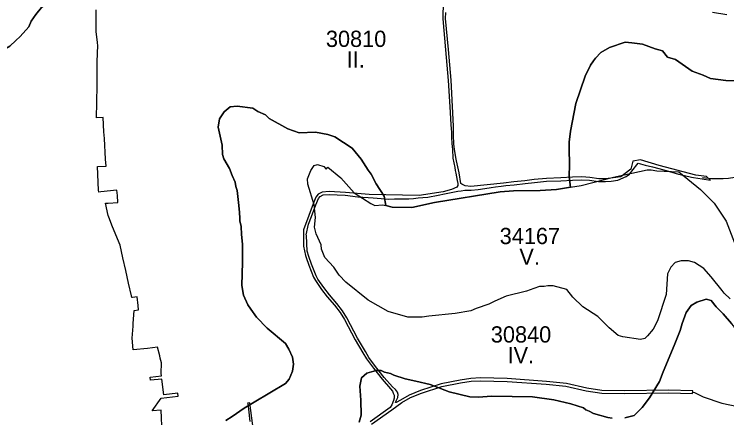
# Model space of a CAD drawing. Extents: x -555509 to -553014, y -1186753 to -1182560.
# Drawn here: x -554443 to -553565, y -1185224 to -1184728 of the extents above; entities that cross this region are included whole.
import ezdxf

# ---------------------------------------------------------------- set-up
doc = ezdxf.new("R2010")
doc.units = 0
for name, color, linetype in [('LEG_6_ZPF', 7, 'Continuous'), ('Level 29', 7, 'Continuous'), ('Level 52', 7, 'Continuous'), ('pěší_tr', 7, 'Continuous')]:
    doc.layers.add(name, color=color, linetype=linetype)

msp = doc.modelspace()

# ---------------------------------------------------------------- linework, layer by layer
at = {"layer": 'LEG_6_ZPF'}
for points in [[(-554364, -1184690.88), (-554375, -1184701), (-554378.81, -1184703.12), (-554394.5, -1184709.13), (-554408.94, -1184719.75), (-554416.12, -1184728.25), (-554421.62, -1184736.63), (-554424.62, -1184743.5), (-554435.25, -1184755.38), (-554440.75, -1184760.38), (-554447.94, -1184767.25), (-554469.56, -1184779.5), (-554542.5, -1184810.5), (-554566.62, -1184818.5), (-554606.06, -1184833.38), (-554611.62, -1184835.88), (-554626.88, -1184837.12)], [(-553757.75, -1184940.88), (-553759.38, -1184927.88), (-553759, -1184912.63), (-553759.38, -1184894), (-553759.38, -1184885.5), (-553757.69, -1184871.88), (-553751.38, -1184838), (-553739.88, -1184804.12), (-553733.12, -1184790.5), (-553729.31, -1184785.38), (-553727.19, -1184782), (-553720.38, -1184775.25), (-553709.81, -1184768.88), (-553690.31, -1184762.5), (-553682.25, -1184763), (-553669.12, -1184764.62), (-553653.44, -1184770.63), (-553644.5, -1184773.13), (-553638.56, -1184780.75), (-553628.38, -1184783.75), (-553608.06, -1184798.13), (-553594.5, -1184802.75), (-553585.56, -1184807), (-553566.5, -1184809.63), (-553544.44, -1184810)], [(-554182.12, -1185228), (-554174.5, -1185223), (-554159.62, -1185212.75), (-554147.31, -1185205.12), (-554108.75, -1185182.25), (-554104.12, -1185177.12), (-554099.88, -1185167), (-554099, -1185158.5), (-554100.25, -1185150), (-554104.5, -1185139.88), (-554108.75, -1185133.12), (-554131.25, -1185114.38), (-554144.38, -1185100.88), (-554151.19, -1185090.75), (-554155, -1185085.63), (-554160.5, -1185073.75), (-554162.62, -1185061.88), (-554161.75, -1185033), (-554161.75, -1185011), (-554163, -1184999.12), (-554163.44, -1184989), (-554164.75, -1184982.12), (-554164.75, -1184978.75), (-554165.12, -1184972), (-554166, -1184963.5), (-554168.12, -1184944.88), (-554169.81, -1184939.75), (-554170.69, -1184934.62), (-554174.5, -1184926.25), (-554177.44, -1184917.75), (-554184.62, -1184905.88), (-554186.38, -1184900.75), (-554186.75, -1184888.88), (-554191.44, -1184866.88), (-554189.75, -1184856.62), (-554184.25, -1184848.12), (-554176.62, -1184841.88), (-554168.12, -1184841), (-554149.06, -1184843.5), (-554142.69, -1184847.75), (-554133.38, -1184851.63), (-554128.69, -1184856.25), (-554105.81, -1184869), (-554091.81, -1184874), (-554071.88, -1184873.25), (-554056.62, -1184875.75), (-554048.12, -1184878.75), (-554026.5, -1184892.75), (-554015.5, -1184906.25), (-554007, -1184919.88), (-554003.19, -1184924.88), (-553997.25, -1184936.75), (-553987.06, -1184952), (-553985, -1184963.5)], [(-553985, -1184963.5), (-553977.31, -1184965.25), (-553953.19, -1184965.62), (-553925.19, -1184959.63), (-553844.19, -1184946.5), (-553828.06, -1184945.25), (-553795, -1184944.88), (-553775.06, -1184943.63), (-553757.75, -1184940.88)], [(-553535.77, -1185130.34), (-553541.5, -1185128.38), (-553549.56, -1185123.75), (-553556.75, -1185111.88), (-553559.69, -1185108.5), (-553569.88, -1185096.62), (-553578.38, -1185088.12), (-553584.75, -1185080.12), (-553590.69, -1185078.38), (-553602.12, -1185082.25), (-553609.31, -1185086.5), (-553615.25, -1185094.88), (-553620.31, -1185108.5), (-553622.88, -1185117), (-553630.06, -1185135.62), (-553643.69, -1185167.88), (-553648.31, -1185179.75), (-553660.62, -1185200.12), (-553669.5, -1185212), (-553679.25, -1185221.75), (-553690.75, -1185224.62)], [(-553706.38, -1185225.12), (-553711.94, -1185224.25), (-553729.31, -1185219.13), (-553734.81, -1185216.25), (-553739.06, -1185214.88), (-553741.62, -1185212.38), (-553757.31, -1185207.25), (-553778.5, -1185202.25), (-553804.75, -1185198.75), (-553854.81, -1185198), (-553871.31, -1185199.25), (-553881.94, -1185198.75), (-553907.38, -1185192.5), (-553930.69, -1185183.5), (-553948.06, -1185179.25), (-553961.19, -1185176.75), (-553975.19, -1185172.12), (-553979.44, -1185170), (-553986.62, -1185168.25), (-553990.88, -1185166.13), (-553997.25, -1185166.13), (-554008.69, -1185169.5), (-554015.06, -1185175.5), (-554017.19, -1185185.62), (-554015.94, -1185202.63), (-554015.5, -1185221.25), (-554018, -1185229.75)]]:
    msp.add_lwpolyline(points, dxfattribs=at)
at = {"layer": 'Level 29'}
for points in [[(-554626.88, -1184837.12), (-554611.62, -1184835.88), (-554606.06, -1184833.38), (-554566.62, -1184818.5), (-554542.5, -1184810.5), (-554469.56, -1184779.5), (-554447.94, -1184767.25), (-554440.75, -1184760.38), (-554435.25, -1184755.38), (-554424.62, -1184743.5), (-554421.62, -1184736.63), (-554416.12, -1184728.25), (-554408.94, -1184719.75), (-554394.5, -1184709.13), (-554378.81, -1184703.12), (-554375, -1184701), (-554364, -1184690.88)], [(-553544.44, -1184810), (-553566.5, -1184809.63), (-553585.56, -1184807), (-553594.5, -1184802.75), (-553608.06, -1184798.13), (-553628.38, -1184783.75), (-553638.56, -1184780.75), (-553644.5, -1184773.13), (-553653.44, -1184770.63), (-553669.12, -1184764.62), (-553682.25, -1184763), (-553690.31, -1184762.5), (-553709.81, -1184768.88), (-553720.38, -1184775.25), (-553727.19, -1184782), (-553729.31, -1184785.38), (-553733.12, -1184790.5), (-553739.88, -1184804.12), (-553751.38, -1184838), (-553757.69, -1184871.88), (-553759.38, -1184885.5), (-553759.38, -1184894), (-553759, -1184912.63), (-553759.38, -1184927.88), (-553757.75, -1184940.88)], [(-553985, -1184963.5), (-553987.06, -1184952), (-553997.25, -1184936.75), (-554003.19, -1184924.88), (-554007, -1184919.88), (-554015.5, -1184906.25), (-554026.5, -1184892.75), (-554048.12, -1184878.75), (-554056.62, -1184875.75), (-554071.88, -1184873.25), (-554091.81, -1184874), (-554105.81, -1184869), (-554128.69, -1184856.25), (-554133.38, -1184851.63), (-554142.69, -1184847.75), (-554149.06, -1184843.5), (-554168.12, -1184841), (-554176.62, -1184841.88), (-554184.25, -1184848.12), (-554189.75, -1184856.62), (-554191.44, -1184866.88), (-554186.75, -1184888.88), (-554186.38, -1184900.75), (-554184.62, -1184905.88), (-554177.44, -1184917.75), (-554174.5, -1184926.25), (-554170.69, -1184934.62), (-554169.81, -1184939.75), (-554168.12, -1184944.88), (-554166, -1184963.5), (-554165.12, -1184972), (-554164.75, -1184978.75), (-554164.75, -1184982.12), (-554163.44, -1184989), (-554163, -1184999.12), (-554161.75, -1185011), (-554161.75, -1185033), (-554162.62, -1185061.88), (-554160.5, -1185073.75), (-554155, -1185085.63), (-554151.19, -1185090.75), (-554144.38, -1185100.88), (-554131.25, -1185114.38), (-554108.75, -1185133.12), (-554104.5, -1185139.88), (-554100.25, -1185150), (-554099, -1185158.5), (-554099.88, -1185167), (-554104.12, -1185177.12), (-554108.75, -1185182.25), (-554147.31, -1185205.12), (-554159.62, -1185212.75), (-554174.5, -1185223), (-554182.12, -1185228)], [(-553561.38, -1185078), (-553568.62, -1185071.25), (-553571.19, -1185067.75), (-553584.75, -1185050.88), (-553593.62, -1185040.63), (-553605.06, -1185033.5), (-553612.69, -1185031.38), (-553621.62, -1185031.38), (-553628.81, -1185033.5), (-553634.31, -1185039), (-553638.56, -1185047.5), (-553639.81, -1185072.88), (-553650.88, -1185105.13), (-553655.94, -1185115.25), (-553663.19, -1185123.75), (-553666.12, -1185126.75), (-553671.62, -1185128), (-553693.25, -1185125), (-553699.19, -1185123.38), (-553710.25, -1185113.63), (-553724.19, -1185100), (-553742.44, -1185088.12), (-553754.75, -1185076.25), (-553762.38, -1185066.5), (-553779.31, -1185062.25), (-553785.69, -1185062.25), (-553790.38, -1185063.12), (-553795.88, -1185063.12), (-553803.06, -1185065.25), (-553812, -1185068.63), (-553837, -1185075), (-553851, -1185081), (-553858.19, -1185084.75), (-553873.88, -1185089.88), (-553880.69, -1185092.75), (-553899.75, -1185096.25), (-553932.38, -1185099.62), (-553940.44, -1185100.88), (-553958.25, -1185100.5), (-553982.44, -1185093.63), (-554007, -1185079.62), (-554034.56, -1185057.63), (-554042.62, -1185049.13), (-554049.38, -1185039), (-554060.44, -1185027.12), (-554064.25, -1185016.88), (-554064.69, -1185011.88), (-554071, -1184998.25), (-554073.12, -1184989.75), (-554071.88, -1184977.88), (-554073.56, -1184962.62), (-554081.19, -1184937.25), (-554081.62, -1184930.38), (-554077.38, -1184920.25), (-554073.56, -1184913.88), (-554069.31, -1184913), (-554061.69, -1184915.13), (-554058.75, -1184918.5), (-554056.62, -1184916), (-554040.5, -1184929.12), (-554023.94, -1184947.75), (-554003.62, -1184961), (-553998.5, -1184963.12), (-553989.19, -1184962.62), (-553985, -1184963.5)], [(-553757.75, -1184940.88), (-553744.56, -1184938.88), (-553704.69, -1184928.25), (-553663.56, -1184919.38), (-553658.5, -1184919.38), (-553651.69, -1184920.63), (-553624.56, -1184922), (-553597.88, -1184943.63), (-553580.94, -1184960.5), (-553566.06, -1184982.62), (-553553.75, -1185014.75)], [(-553757.75, -1184940.88), (-553775.06, -1184943.63), (-553795, -1184944.88), (-553828.06, -1184945.25), (-553844.19, -1184946.5), (-553925.19, -1184959.63), (-553953.19, -1184965.62), (-553977.31, -1184965.25), (-553985, -1184963.5)], [(-553690.75, -1185224.62), (-553679.25, -1185221.75), (-553669.5, -1185212), (-553660.62, -1185200.12), (-553648.31, -1185179.75), (-553643.69, -1185167.88), (-553630.06, -1185135.62), (-553622.88, -1185117), (-553620.31, -1185108.5), (-553615.25, -1185094.88), (-553609.31, -1185086.5), (-553602.12, -1185082.25), (-553590.69, -1185078.38), (-553584.75, -1185080.12), (-553578.38, -1185088.12), (-553569.88, -1185096.62), (-553559.69, -1185108.5)], [(-554018, -1185229.75), (-554015.5, -1185221.25), (-554015.94, -1185202.63), (-554017.19, -1185185.62), (-554015.06, -1185175.5), (-554008.69, -1185169.5), (-553997.25, -1185166.13), (-553990.88, -1185166.13), (-553986.62, -1185168.25), (-553979.44, -1185170), (-553975.19, -1185172.12), (-553961.19, -1185176.75), (-553948.06, -1185179.25), (-553930.69, -1185183.5), (-553907.38, -1185192.5), (-553881.94, -1185198.75), (-553871.31, -1185199.25), (-553854.81, -1185198), (-553804.75, -1185198.75), (-553778.5, -1185202.25), (-553757.31, -1185207.25), (-553741.62, -1185212.38), (-553739.06, -1185214.88), (-553734.81, -1185216.25), (-553729.31, -1185219.13), (-553711.94, -1185224.25), (-553706.38, -1185225.12)]]:
    msp.add_lwpolyline(points, dxfattribs=at)
at = {"layer": 'Level 52'}
for points in [[(-554261.68, -1185169.84), (-554261.41, -1185156.97), (-554262.83, -1185151.21), (-554263.56, -1185148.28), (-554266.16, -1185137.73), (-554278.63, -1185139.14), (-554296.23, -1185140.99), (-554297.61, -1185126.6), (-554296.34, -1185111.77), (-554296.07, -1185108.67), (-554294.99, -1185092.44), (-554289.59, -1185091.84), (-554290.23, -1185086.45), (-554291.51, -1185075.66), (-554296.96, -1185076.3), (-554297.89, -1185076.4), (-554298.34, -1185074.44), (-554301.86, -1185058.86), (-554305.39, -1185043.29), (-554308.92, -1185027.72), (-554312.44, -1185012.11), (-554321.72, -1184989.72), (-554326.07, -1184977.51), (-554326.84, -1184975.49), (-554330.11, -1184960.46), (-554326.99, -1184960.31), (-554314.96, -1184959.76), (-554315.56, -1184950.89), (-554316.22, -1184944.55), (-554336.13, -1184946.57), (-554338.7, -1184946.83), (-554338.8, -1184944.45), (-554340.04, -1184915.42), (-554329.6, -1184914.77), (-554330.13, -1184906.31), (-554330.65, -1184897.85), (-554331.18, -1184889.39), (-554331.7, -1184880.94), (-554332.23, -1184872.48), (-554332.76, -1184864.02), (-554332.79, -1184863.52), (-554333.31, -1184855.07), (-554341.45, -1184855.6), (-554340.98, -1184836.51), (-554340.45, -1184815.27), (-554340.55, -1184800.62), (-554340.65, -1184791.15), (-554340.66, -1184789.6), (-554340.41, -1184787.86), (-554340.01, -1184775.1), (-554339.91, -1184767.31), (-554340.34, -1184762.35), (-554341.66, -1184749.64), (-554341.75, -1184736.88), (-554341.86, -1184722.43)], [(-554260.7, -1185244.02), (-554261.67, -1185215.2), (-554272.84, -1185216.03), (-554261.68, -1185200.5), (-554240.79, -1185197.9), (-554241.26, -1185194.32), (-554258.65, -1185196.28), (-554260.88, -1185176.8), (-554274.69, -1185178.31), (-554275.12, -1185174.33), (-554261.34, -1185172.83), (-554261.68, -1185169.84)]]:
    msp.add_lwpolyline(points, dxfattribs=at)
at = {"layer": 'pěší_tr'}
for points in [[(-553914.88, -1184618.77), (-553913.5, -1184657.11), (-553913.76, -1184677.32), (-553913.68, -1184689.88), (-553913.93, -1184709.71), (-553914.84, -1184725.59), (-553915.05, -1184733.49), (-553911.52, -1184771.82), (-553908.33, -1184809.34)], [(-553708.26, -1184929.83), (-553714.84, -1184930.45), (-553722.95, -1184930.39), (-553733.92, -1184928.85), (-553743.8, -1184928.15), (-553755.36, -1184928.52), (-553769.66, -1184929.29), (-553787.44, -1184930), (-553802.57, -1184931.39), (-553813.96, -1184932.77), (-553827.39, -1184934.32), (-553840.31, -1184935.75), (-553880.58, -1184939.8), (-553887.3, -1184939.11), (-553891.43, -1184937.22), (-553892.7, -1184936.1), (-553894.95, -1184923.21), (-553898.35, -1184908.26), (-553898.66, -1184906.26), (-553900.51, -1184894.48), (-553901.56, -1184887.51), (-553901.67, -1184876.74), (-553901.93, -1184865.66), (-553902.94, -1184841.66), (-553904.84, -1184809.09), (-553908.03, -1184771.51), (-553911.55, -1184733.38), (-553911.34, -1184725.74)], [(-553583.15, -1184725.44), (-553565.13, -1184728.17)], [(-553595.39, -1184929), (-553584.22, -1184929.89), (-553569.97, -1184930.17), (-553563.46, -1184929.76), (-553547.71, -1184927.08), (-553542.91, -1184924.48), (-553537.7, -1184919.34), (-553537.84, -1184905.3), (-553538.53, -1184891.19), (-553535.24, -1184841.65), (-553533.25, -1184816.23), (-553532.57, -1184768.41), (-553530.79, -1184751.49), (-553530.85, -1184731.28)], [(-553908.33, -1184809.34), (-553908.33, -1184809.34), (-553906.44, -1184841.86), (-553905.26, -1184863.49), (-553905.16, -1184864.48), (-553904.76, -1184868.35), (-553904.5, -1184874), (-553904.23, -1184879.65), (-553903.72, -1184887.01), (-553903.38, -1184890.69), (-553903.04, -1184894.37), (-553902.74, -1184905), (-553901.55, -1184910.75), (-553900.36, -1184916.5), (-553899.67, -1184920.24), (-553899.04, -1184923.67), (-553897.19, -1184932.74), (-553896.54, -1184936.39), (-553896.69, -1184938.72), (-553897.8, -1184940.7), (-553904.44, -1184943.46), (-553914.4, -1184946.57), (-553944.13, -1184950.79), (-554005.64, -1184949.81), (-554034.98, -1184947.14), (-554054.99, -1184946.1), (-554063.37, -1184946.83), (-554068.43, -1184949.41), (-554071.21, -1184953.09), (-554074.58, -1184961.16), (-554080.1, -1184975.65), (-554086.4, -1184993.22), (-554086.57, -1185009.18), (-554086.61, -1185013.34), (-554084, -1185024.83), (-554083.1, -1185027.29), (-554080.03, -1185036.82), (-554074.24, -1185051.48), (-554071.95, -1185055.67), (-554064.37, -1185066.47), (-554057.22, -1185075.48), (-554048.4, -1185085.93), (-554041.5, -1185094.96), (-554036.24, -1185103.41), (-554023.07, -1185128.41), (-554013.33, -1185144.66), (-554009.15, -1185152.04), (-554000.46, -1185163.6), (-553989.74, -1185177.08), (-553979.56, -1185188.82), (-553977.12, -1185191.81), (-553976, -1185194.31), (-553975.05, -1185196.72), (-553975.05, -1185200.16), (-553975.74, -1185203.09), (-553977.89, -1185208.6), (-553979.93, -1185211.82), (-554004.63, -1185229.29)], [(-553835.72, -1185176.2), (-553868.46, -1185175.42), (-553880.32, -1185176.03), (-553893.8, -1185178.03), (-553917.1, -1185182.79), (-553942.58, -1185190.77), (-553956.27, -1185196.52), (-553967.29, -1185202.68), (-553972.38, -1185205.67), (-553973.24, -1185205.76), (-553973.41, -1185205.33), (-553971.95, -1185202.92), (-553970.4, -1185199.56), (-553970.06, -1185195.86), (-553970.74, -1185193.1), (-553973.16, -1185189.66), (-553976.91, -1185186.53), (-553987.05, -1185174.85), (-553997.69, -1185161.46), (-554006.22, -1185150.12), (-554010.31, -1185142.9), (-554020.02, -1185126.69), (-554033.2, -1185101.66), (-554038.62, -1185092.97), (-554045.67, -1185083.74), (-554054.51, -1185073.27), (-554061.57, -1185064.37), (-554068.97, -1185053.82), (-554071.07, -1185049.99), (-554076.73, -1185035.64), (-554079.77, -1185026.22), (-554081.96, -1185019.29), (-554082.99, -1185000.29), (-554083.05, -1184999.19), (-554080.23, -1184986.06), (-554076.83, -1184976.89), (-554071.33, -1184962.45), (-554068.16, -1184954.85), (-554066.12, -1184952.16), (-554062.39, -1184950.26), (-554054.93, -1184949.61), (-554035.16, -1184950.64), (-554019.59, -1184952.44), (-554000.7, -1184953.73), (-553990.98, -1184954.51), (-553981.44, -1184955.31), (-553974.28, -1184955.24), (-553968.26, -1184955.22), (-553962.26, -1184955.2), (-553956.95, -1184955.17), (-553951.28, -1184954.65), (-553945.43, -1184954.06), (-553939.61, -1184953.44), (-553933.25, -1184952.85), (-553920.87, -1184950.42), (-553912.83, -1184949.06), (-553904.57, -1184947.31), (-553896.35, -1184945.85), (-553892.21, -1184945.11), (-553888.05, -1184944.56), (-553879.97, -1184944.36), (-553871.48, -1184943.44), (-553863.47, -1184942.38), (-553855.55, -1184941.34), (-553850.2, -1184940.25), (-553843.34, -1184939.61), (-553837.41, -1184938.84), (-553826.99, -1184937.79), (-553813.55, -1184936.24), (-553802.2, -1184934.87), (-553787.2, -1184933.5), (-553769.5, -1184932.79), (-553755.21, -1184932.01), (-553743.87, -1184931.65), (-553734.29, -1184932.33), (-553723.21, -1184933.89), (-553714.69, -1184933.95), (-553707.93, -1184933.32), (-553699.64, -1184932.23), (-553689.27, -1184927.53), (-553685.36, -1184924.78), (-553676.31, -1184913.4), (-553674.57, -1184911.31), (-553665.75, -1184913.68), (-553656.79, -1184915.79), (-553648.89, -1184917.93), (-553640.1, -1184920.11), (-553624.9, -1184924.81), (-553617.58, -1184926.39), (-553609, -1184928.41), (-553606.18, -1184928.98), (-553595.83, -1184930.5), (-553585.32, -1184931.98), (-553590.45, -1184927.47), (-553603.64, -1184926.15), (-553648.73, -1184914.22), (-553671.51, -1184907.25), (-553680.88, -1184908.93), (-553683.6, -1184918.47), (-553695.72, -1184927.94), (-553708.26, -1184929.83)], [(-554002.65, -1185232.18), (-553977.91, -1185214.68), (-553965.58, -1185205.74), (-553954.73, -1185199.67), (-553941.38, -1185194.06), (-553916.22, -1185186.19), (-553893.19, -1185181.48), (-553879.98, -1185179.52), (-553868.42, -1185178.92), (-553835.89, -1185179.69), (-553787.65, -1185183.31), (-553763.41, -1185185.79), (-553738.48, -1185191.42), (-553719.35, -1185194.38), (-553690.96, -1185194.72), (-553637.23, -1185193.86), (-553607.39, -1185194.68), (-553607.3, -1185191.18), (-553637.21, -1185190.36), (-553690.96, -1185191.22), (-553719.06, -1185190.88), (-553737.82, -1185187.98), (-553762.84, -1185182.33), (-553787.34, -1185179.82), (-553835.72, -1185176.2)], [(-553607.34, -1185192.93), (-553605.19, -1185193.28), (-553594.36, -1185198.77), (-553571.62, -1185206.58), (-553541.88, -1185212.74)], [(-554146.99, -1185250.03), (-554152.61, -1185206.04), (-554155.32, -1185206.34), (-554155.2, -1185207.34), (-554154.41, -1185213.9), (-554152.6, -1185228.9)]]:
    msp.add_lwpolyline(points, dxfattribs=at)

# ---------------------------------------------------------------- texts
at = {"layer": 'Level 29'}
for s, p in [('30810', (-554058.95, -1184768.22)), ('II.', (-554033.28, -1184793.67)), ('34167', (-553844.98, -1185010.81)), ('V.', (-553820.74, -1185036.26)), ('30840', (-553855.88, -1185131.92)), ('IV.', (-553835.3, -1185157.38))]:
    msp.add_text(s, height=20, dxfattribs=at).set_placement(p)

doc.saveas('drawing.dxf')
